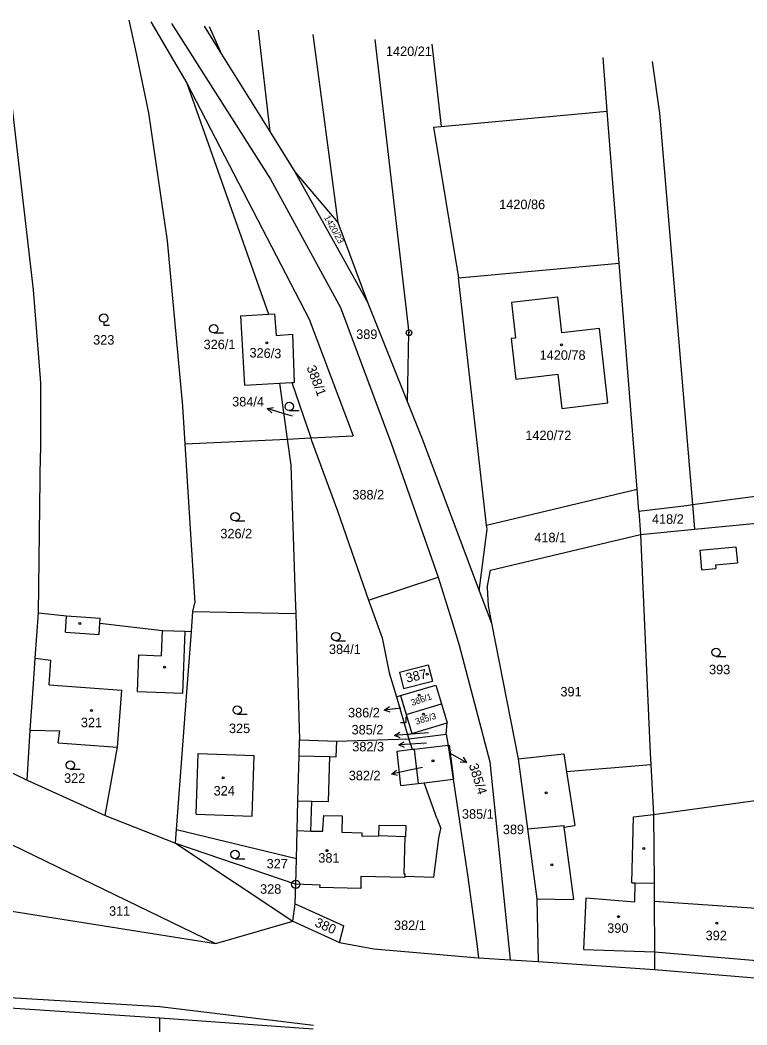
# Model space of a CAD drawing. Extents: x -779596 to -776743, y -1030330 to -1024513.
# Drawn here: x -778185.6 to -778055.6, y -1024710.7 to -1024531 of the extents above; entities that cross this region are included whole.
import ezdxf

# ---------------------------------------------------------------- set-up
doc = ezdxf.new("R2010")
doc.units = 0
for name, color, linetype in [('hranice parcel', 7, 'Continuous'), ('hranice vnitřní', 7, 'Continuous'), ('kultura', 7, 'Continuous'), ('Kód', 7, 'Continuous'), ('č_ parcel šipka', 7, 'Continuous'), ('č_pacel stav_', 7, 'Continuous'), ('č_parcel poz_', 7, 'Continuous')]:
    doc.layers.add(name, color=color, linetype=linetype)

msp = doc.modelspace()

# ---------------------------------------------------------------- linework, layer by layer
at = {"layer": 'hranice parcel'}
for points in [[(-778166.101, -1024530.961), (-778165.01, -1024536.11)], [(-778162.172, -1024531.271), (-778159.31, -1024536.15)], [(-778158.503, -1024531.561), (-778140.78, -1024559.41)], [(-778152.673, -1024532.022), (-778149.53, -1024537.06)], [(-778151.731, -1024532.097), (-778149.53, -1024537.06)], [(-778142.993, -1024532.788), (-778140.9, -1024550.9)], [(-778133.2, -1024533.562), (-778128.72, -1024567.18)], [(-778122.155, -1024534.435), (-778116.03, -1024586.88)], [(-778111.953, -1024535.242), (-778110.27, -1024549.98)], [(-778188.22, -1024535.94), (-778183.2, -1024579.2)], [(-778165.01, -1024536.11), (-778162.59, -1024547.55)], [(-778159.31, -1024536.15), (-778155.72, -1024542.27)], [(-778149.53, -1024537.06), (-778140.9, -1024550.9)], [(-778080.57, -1024547.24), (-778081.327, -1024537.663)], [(-778072.52, -1024538.359), (-778071.24, -1024547.6)], [(-778155.72, -1024542.27), (-778133.89, -1024584.45)], [(-778155.72, -1024542.27), (-778141.16, -1024583.54)], [(-778162.59, -1024547.55), (-778159.29, -1024570.46)], [(-778110.27, -1024549.98), (-778080.57, -1024547.24)], [(-778078.43, -1024574.41), (-778080.57, -1024547.24)], [(-778071.24, -1024547.6), (-778065.31, -1024617.62)], [(-778111.65, -1024550.11), (-778110.27, -1024549.98)], [(-778111.65, -1024550.11), (-778107.19, -1024577.03)], [(-778140.9, -1024550.9), (-778136.42, -1024558.08)], [(-778136.42, -1024558.08), (-778123.43, -1024581.39)], [(-778136.42, -1024558.08), (-778128.72, -1024567.18)], [(-778140.78, -1024559.41), (-778128.27, -1024582.35)], [(-778128.72, -1024567.18), (-778123.43, -1024581.39)], [(-778159.29, -1024570.46), (-778156.54, -1024599.98)], [(-778107.19, -1024577.03), (-778078.43, -1024574.41)], [(-778075.24, -1024614.87), (-778078.43, -1024574.41)], [(-778102.14, -1024621.29), (-778107.19, -1024577.03)], [(-778183.2, -1024579.2), (-778181.9, -1024595.82)], [(-778089.42, -1024580.5), (-778097.68, -1024581.48)], [(-778088.69, -1024586.87), (-778089.42, -1024580.5)], [(-778128.27, -1024582.35), (-778119.12, -1024606.78)], [(-778123.43, -1024581.39), (-778116.3, -1024599.27)], [(-778097.68, -1024581.48), (-778096.95, -1024587.84)], [(-778146.13, -1024583.85), (-778141.16, -1024583.54)], [(-778146.13, -1024583.85), (-778145.46, -1024596.25)], [(-778141.16, -1024583.54), (-778140.06, -1024583.47)], [(-778140.06, -1024583.47), (-778139.76, -1024587.37)], [(-778133.89, -1024584.45), (-778125.99, -1024605.33)], [(-778081.93, -1024586.11), (-778088.69, -1024586.87)], [(-778080.44, -1024599.44), (-778081.93, -1024586.11)], [(-778139.76, -1024587.37), (-778136.84, -1024587.15)], [(-778136.84, -1024587.15), (-778136.54, -1024595.76)], [(-778116.3, -1024599.27), (-778116.03, -1024586.88)], [(-778096.95, -1024587.84), (-778097.75, -1024587.91)], [(-778097.75, -1024587.91), (-778096.94, -1024595.18)], [(-778096.94, -1024595.18), (-778089.39, -1024594.31)], [(-778089.39, -1024594.31), (-778088.7, -1024600.4)], [(-778181.9, -1024595.82), (-778181.89, -1024608.42)], [(-778145.46, -1024596.25), (-778139.2, -1024595.91)], [(-778139.2, -1024595.91), (-778136.97, -1024595.79)], [(-778139.2, -1024595.91), (-778137.82, -1024605.88)], [(-778136.97, -1024595.79), (-778136.54, -1024595.76)], [(-778136.97, -1024595.79), (-778133.6, -1024605.68)], [(-778156.54, -1024599.98), (-778156.12, -1024606.73)], [(-778116.3, -1024599.27), (-778113.56, -1024606.14)], [(-778088.7, -1024600.4), (-778080.44, -1024599.44)], [(-778156.12, -1024606.73), (-778137.82, -1024605.88)], [(-778137.82, -1024605.88), (-778133.6, -1024605.68)], [(-778137.82, -1024605.88), (-778137.16, -1024610.58)], [(-778133.6, -1024605.68), (-778125.99, -1024605.33)], [(-778133.6, -1024605.68), (-778133.45, -1024606.15)], [(-778156.12, -1024606.73), (-778154.34, -1024635.17)], [(-778133.45, -1024606.15), (-778128.79, -1024618.71)], [(-778119.12, -1024606.78), (-778110.78, -1024630.57)], [(-778113.56, -1024606.14), (-778103.45, -1024633.03)], [(-778182.26, -1024636.99), (-778181.89, -1024608.42)], [(-778137.16, -1024610.58), (-778136.35, -1024634.3)], [(-778102.14, -1024621.29), (-778075.24, -1024614.87)], [(-778074.93, -1024618.78), (-778075.24, -1024614.87)], [(-778065.31, -1024617.62), (-778042.46, -1024614.57)], [(-778074.93, -1024618.78), (-778066.42, -1024617.77)], [(-778066.42, -1024617.77), (-778065.31, -1024617.62)], [(-778065.31, -1024617.62), (-778064.94, -1024622)], [(-778128.79, -1024618.71), (-778123.25, -1024634.7)], [(-778074.93, -1024618.78), (-778074.6, -1024622.94)], [(-778103.45, -1024633.03), (-778102.06, -1024622)], [(-778102.06, -1024622), (-778102.14, -1024621.29)], [(-778074.6, -1024622.94), (-778064.94, -1024622)], [(-778064.94, -1024622), (-778048.89, -1024620.45)], [(-778101.43, -1024629.35), (-778074.6, -1024622.94)], [(-778074.6, -1024622.94), (-778072.88, -1024662.1)], [(-778102.05, -1024632.52), (-778101.43, -1024629.35)], [(-778123.25, -1024634.7), (-778110.78, -1024630.57)], [(-778110.78, -1024630.57), (-778108.44, -1024638.2)], [(-778102.05, -1024632.52), (-778101.89, -1024635.72)], [(-778136.35, -1024634.3), (-778136.25, -1024637.07)], [(-778123.25, -1024634.7), (-778120.79, -1024641.44)], [(-778103.45, -1024633.03), (-778101.27, -1024638.84)], [(-778154.66, -1024636.73), (-778154.34, -1024635.17)], [(-778101.89, -1024635.72), (-778101.27, -1024638.84)], [(-778182.84, -1024645.1), (-778182.26, -1024636.99)], [(-778182.26, -1024636.99), (-778177.25, -1024637.52)], [(-778177.25, -1024637.52), (-778171.26, -1024637.91)], [(-778171.32, -1024638.81), (-778171.26, -1024637.91)], [(-778154.93, -1024640.32), (-778154.66, -1024636.73)], [(-778154.66, -1024636.73), (-778136.25, -1024637.07)], [(-778136.25, -1024637.07), (-778135.58, -1024659.69)], [(-778108.44, -1024638.2), (-778107.04, -1024642.76)], [(-778171.32, -1024638.81), (-778160.08, -1024640.12)], [(-778160.08, -1024640.12), (-778156.04, -1024640.27)], [(-778101.27, -1024638.84), (-778096.49, -1024663.08)], [(-778156.04, -1024640.27), (-778154.93, -1024640.32)], [(-778155.8, -1024651.95), (-778154.93, -1024640.32)], [(-778120.79, -1024641.44), (-778119.56, -1024647.69)], [(-778107.04, -1024642.76), (-778101.56, -1024663.63)], [(-778183.16, -1024649.64), (-778182.84, -1024645.1)], [(-778117.72, -1024647.59), (-778112.59, -1024646.28)], [(-778112.59, -1024646.28), (-778111.84, -1024649.19)], [(-778119.56, -1024647.69), (-778118.28, -1024651.99)], [(-778117.72, -1024647.59), (-778116.98, -1024650.51)], [(-778183.79, -1024657.94), (-778183.16, -1024649.64)], [(-778117.52, -1024651.76), (-778111.21, -1024649.88)], [(-778116.98, -1024650.51), (-778111.84, -1024649.19)], [(-778111.21, -1024649.88), (-778110.2, -1024653.27)], [(-778157.58, -1024675.7), (-778155.8, -1024651.95)], [(-778118.28, -1024651.99), (-778117.52, -1024651.76)], [(-778118.28, -1024651.99), (-778116.26, -1024658.77)], [(-778117.52, -1024651.76), (-778116.5, -1024655.15)], [(-778116.5, -1024655.15), (-778110.2, -1024653.27)], [(-778110.2, -1024653.27), (-778109.19, -1024656.66)], [(-778116.5, -1024655.15), (-778115.49, -1024658.54)], [(-778184.31, -1024666.91), (-778183.79, -1024657.94)], [(-778183.79, -1024657.94), (-778178.45, -1024658.1)], [(-778178.77, -1024660.2), (-778178.45, -1024658.1)], [(-778115.49, -1024658.54), (-778109.19, -1024656.66)], [(-778109.35, -1024658.65), (-778109.19, -1024656.66)], [(-778201.09, -1024658.8), (-778184.31, -1024666.91)], [(-778135.65, -1024662.56), (-778135.58, -1024659.69)], [(-778135.58, -1024659.69), (-778128.92, -1024659.91)], [(-778128.92, -1024659.91), (-778116.03, -1024659.53)], [(-778116.26, -1024658.77), (-778115.49, -1024658.54)], [(-778116.26, -1024658.77), (-778116.03, -1024659.53)], [(-778116.03, -1024659.53), (-778109.35, -1024658.65)], [(-778115.37, -1024661.42), (-778116.03, -1024659.53)], [(-778109.35, -1024658.65), (-778109.04, -1024660.69)], [(-778178.77, -1024660.2), (-778168.17, -1024660.97)], [(-778170.34, -1024673.22), (-778168.17, -1024660.97)], [(-778115.37, -1024661.42), (-778118.19, -1024661.76)], [(-778115.08, -1024661.39), (-778115.37, -1024661.42)], [(-778109.04, -1024660.69), (-778115.08, -1024661.39)], [(-778109.04, -1024660.69), (-778108.81, -1024660.66)], [(-778109.04, -1024660.69), (-778108.13, -1024666.73)], [(-778108.81, -1024660.66), (-778108.07, -1024666.73)], [(-778154.07, -1024672.99), (-778153.71, -1024662.15)], [(-778153.71, -1024662.15), (-778143.72, -1024662.48)], [(-778144.08, -1024673.32), (-778143.72, -1024662.48)], [(-778135.88, -1024670.57), (-778135.65, -1024662.56)], [(-778118.19, -1024661.76), (-778117.53, -1024667.82)], [(-778096.49, -1024663.08), (-778088.36, -1024662.21)], [(-778096.49, -1024663.08), (-778094.83, -1024675.59)], [(-778088.36, -1024662.21), (-778087.88, -1024665.34)], [(-778072.88, -1024662.1), (-778072.77, -1024664.1)], [(-778101.56, -1024663.63), (-778097.93, -1024699.01)], [(-778087.88, -1024665.34), (-778072.77, -1024664.1)], [(-778072.77, -1024664.1), (-778072.27, -1024673.03)], [(-778184.31, -1024666.91), (-778170.34, -1024673.22)], [(-778113.29, -1024667.35), (-778108.13, -1024666.73)], [(-778108.13, -1024666.73), (-778105.48, -1024684.24)], [(-778108.07, -1024666.73), (-778108.13, -1024666.73)], [(-778117.53, -1024667.82), (-778114.37, -1024667.47)], [(-778114.37, -1024667.47), (-778113.29, -1024667.35)], [(-778111.05, -1024673.72), (-778113.29, -1024667.35)], [(-778136.03, -1024675.91), (-778135.88, -1024670.57)], [(-778072.27, -1024673.03), (-778047.16, -1024669.58)], [(-778170.34, -1024673.22), (-778157.77, -1024678.19)], [(-778154.07, -1024672.99), (-778144.08, -1024673.32)], [(-778111.05, -1024673.72), (-778110.33, -1024675.52)], [(-778072.27, -1024673.03), (-778072.19, -1024685.34)], [(-778193.66, -1024675.24), (-778174.57, -1024684.5)], [(-778157.77, -1024678.19), (-778157.58, -1024675.7)], [(-778157.58, -1024675.7), (-778136.16, -1024680.88)], [(-778136.16, -1024680.88), (-778136.03, -1024675.91)], [(-778110.69, -1024677.28), (-778110.33, -1024675.52)], [(-778094.83, -1024675.59), (-778093.18, -1024688.11)], [(-778111.6, -1024684.24), (-778110.69, -1024677.28)], [(-778157.77, -1024678.19), (-778136.79, -1024692.14)], [(-778157.77, -1024678.19), (-778136.27, -1024685.52)], [(-778136.27, -1024685.52), (-778136.16, -1024680.88)], [(-778174.57, -1024684.5), (-778150.63, -1024696.12)], [(-778124.61, -1024684.13), (-778124.66, -1024686.25)], [(-778116.78, -1024684.3), (-778124.61, -1024684.13)], [(-778116.78, -1024684.07), (-778111.6, -1024684.24)], [(-778116.78, -1024684.07), (-778116.78, -1024684.3)], [(-778105.48, -1024684.24), (-778103.97, -1024695.71)], [(-778136.4, -1024689.02), (-778136.27, -1024685.52)], [(-778131.92, -1024685.69), (-778136.27, -1024685.52)], [(-778131.94, -1024686.11), (-778131.92, -1024685.69)], [(-778124.66, -1024686.25), (-778131.94, -1024686.11)], [(-778072.19, -1024685.34), (-778072.17, -1024688.53)], [(-778093.18, -1024688.11), (-778092.94, -1024699.3)], [(-778072.17, -1024688.53), (-778072.11, -1024697.57)], [(-778195.72, -1024688.95), (-778150.63, -1024696.12)], [(-778136.79, -1024692.14), (-778136.4, -1024689.02)], [(-778136.4, -1024689.02), (-778127.67, -1024692.93)], [(-778148.71, -1024695.55), (-778136.79, -1024692.14)], [(-778136.79, -1024692.14), (-778128.43, -1024695.93)], [(-778128.43, -1024695.93), (-778127.67, -1024692.93)], [(-778150.63, -1024696.12), (-778148.71, -1024695.55)], [(-778103.97, -1024695.71), (-778103.58, -1024698.68)], [(-778128.43, -1024695.93), (-778122.31, -1024697.09)], [(-778122.31, -1024697.09), (-778103.58, -1024698.68)], [(-778072.11, -1024697.57), (-778072.09, -1024700.76)], [(-778103.58, -1024698.68), (-778097.93, -1024699.01)], [(-778097.93, -1024699.01), (-778092.94, -1024699.3)], [(-778092.94, -1024699.3), (-778072.09, -1024700.76)], [(-778072.09, -1024700.76), (-778049.13, -1024702.66)], [(-778198.44, -1024705.1), (-778160.55, -1024707.39)], [(-778188.31, -1024707.53), (-778160.55, -1024709.39)], [(-778160.55, -1024707.39), (-778133.07, -1024710.69)], [(-778160.63, -1024741.23), (-778160.55, -1024709.39)], [(-778160.55, -1024709.39), (-778133.13, -1024711.38)]]:
    msp.add_lwpolyline(points, dxfattribs=at)
at = {"layer": 'hranice vnitřní'}
for points in [[(-778064.02, -1024625.76), (-778057.56, -1024625.18)], [(-778057.56, -1024625.18), (-778057.3, -1024628.03)], [(-778064.02, -1024625.76), (-778063.7, -1024629.28)], [(-778063.7, -1024629.28), (-778061.13, -1024629.05)], [(-778061.19, -1024628.38), (-778057.3, -1024628.03)], [(-778061.19, -1024628.38), (-778061.13, -1024629.05)], [(-778177.44, -1024640.43), (-778177.25, -1024637.52)], [(-778171.45, -1024640.82), (-778171.32, -1024638.81)], [(-778160.25, -1024644.64), (-778160.08, -1024640.12)], [(-778177.44, -1024640.43), (-778171.45, -1024640.82)], [(-778156.47, -1024651.35), (-778156.04, -1024640.27)], [(-778182.84, -1024645.1), (-778180.07, -1024645.46)], [(-778180.39, -1024649.84), (-778180.07, -1024645.46)], [(-778164.59, -1024651.04), (-778164.34, -1024644.49)], [(-778164.34, -1024644.49), (-778160.25, -1024644.64)], [(-778180.39, -1024649.84), (-778167.34, -1024650.8)], [(-778168.17, -1024660.97), (-778167.34, -1024650.8)], [(-778164.59, -1024651.04), (-778156.47, -1024651.35)], [(-778129.06, -1024662.75), (-778128.92, -1024659.91)], [(-778115.08, -1024661.39), (-778114.37, -1024667.47)], [(-778135.65, -1024662.56), (-778130.18, -1024662.67)], [(-778130.4, -1024670.72), (-778130.18, -1024662.67)], [(-778130.18, -1024662.67), (-778129.06, -1024662.75)], [(-778087.88, -1024665.34), (-778086.39, -1024675)], [(-778135.88, -1024670.57), (-778133.4, -1024670.64)], [(-778133.55, -1024676.01), (-778133.4, -1024670.64)], [(-778133.4, -1024670.64), (-778130.4, -1024670.72)], [(-778131.4, -1024675.58), (-778131.22, -1024673.24)], [(-778131.22, -1024673.24), (-778127.99, -1024673.28)], [(-778127.99, -1024673.28), (-778128.03, -1024676.18)], [(-778076.15, -1024685.25), (-778075.9, -1024673.46)], [(-778075.9, -1024673.46), (-778072.27, -1024673.03)], [(-778136.03, -1024675.91), (-778133.55, -1024676.01)], [(-778133.55, -1024676.01), (-778131.43, -1024676.04)], [(-778131.43, -1024676.04), (-778131.4, -1024675.58)], [(-778121.39, -1024676.85), (-778121.37, -1024674.96)], [(-778121.37, -1024674.96), (-778116.59, -1024675.03)], [(-778116.59, -1024675.03), (-778116.64, -1024677.05)], [(-778094.83, -1024675.59), (-778088.34, -1024674.99)], [(-778088.34, -1024674.99), (-778088.31, -1024675.28)], [(-778088.31, -1024675.28), (-778086.39, -1024675)], [(-778088.31, -1024675.28), (-778086.59, -1024688.24)], [(-778128.03, -1024676.18), (-778124.45, -1024676.33)], [(-778124.45, -1024676.33), (-778124.46, -1024676.91)], [(-778124.46, -1024676.91), (-778121.39, -1024676.85)], [(-778116.78, -1024677.05), (-778121.39, -1024676.85)], [(-778116.78, -1024677.05), (-778116.94, -1024683.65)], [(-778116.64, -1024677.05), (-778116.78, -1024677.05)], [(-778116.94, -1024683.65), (-778116.77, -1024683.65)], [(-778116.77, -1024683.65), (-778116.78, -1024684.07)], [(-778076.15, -1024685.25), (-778075.55, -1024685.27)], [(-778075.62, -1024688.65), (-778075.55, -1024685.27)], [(-778075.55, -1024685.27), (-778072.19, -1024685.34)], [(-778093.18, -1024688.11), (-778086.59, -1024688.24)], [(-778084.76, -1024697.18), (-778084.33, -1024687.93)], [(-778084.33, -1024687.93), (-778075.62, -1024688.65)], [(-778072.17, -1024688.53), (-778053.89, -1024689.78)], [(-778084.76, -1024697.18), (-778072.11, -1024697.57)], [(-778072.11, -1024697.57), (-778048.92, -1024699.55)]]:
    msp.add_lwpolyline(points, dxfattribs=at)
at = {"layer": 'kultura'}
for points in [[(-778170.6, -1024585.01), (-778170.6, -1024585.51), (-778169.577, -1024585.51)], [(-778150.94, -1024586.91), (-778149.19, -1024586.91)], [(-778137.43, -1024600.8), (-778135.68, -1024600.8)], [(-778147.1, -1024620.54), (-778145.35, -1024620.54)], [(-778129.1, -1024641.96), (-778127.35, -1024641.96)], [(-778061.1, -1024644.78), (-778059.35, -1024644.78)], [(-778146.73, -1024655.1), (-778144.98, -1024655.1)], [(-778117.53, -1024656.58), (-778116.53, -1024656.58), (-778116.53, -1024655.58)], [(-778176.58, -1024664.94), (-778174.83, -1024664.94)], [(-778147.13, -1024680.94), (-778145.38, -1024680.94)]]:
    msp.add_lwpolyline(points, dxfattribs=at)
for centre, radius in [((-778170.6, -1024584.26), 0.75), ((-778150.94, -1024586.16), 0.75), ((-778141.43, -1024588.68), 0.175), ((-778088.73, -1024589.02), 0.175), ((-778137.43, -1024600.05), 0.75), ((-778147.1, -1024619.79), 0.75), ((-778174.89, -1024638.87), 0.175), ((-778129.1, -1024641.21), 0.75), ((-778061.1, -1024644.03), 0.75), ((-778159.72, -1024646.67), 0.175), ((-778112.76, -1024647.92), 0.175), ((-778114.19, -1024651.69), 0.175), ((-778172.78, -1024654.46), 0.175), ((-778146.73, -1024654.35), 0.75), ((-778113.43, -1024655.1), 0.175), ((-778108.89, -1024660.84), 0.118), ((-778176.58, -1024664.19), 0.75), ((-778111.73, -1024663.43), 0.175), ((-778149.26, -1024666.47), 0.175), ((-778091.49, -1024669.14), 0.175), ((-778147.13, -1024680.19), 0.75), ((-778130.68, -1024679.5), 0.175), ((-778074.02, -1024679.12), 0.175), ((-778090.47, -1024682.06), 0.175), ((-778078.57, -1024691.31), 0.175), ((-778060.97, -1024692.48), 0.175)]:
    msp.add_circle(centre, radius, dxfattribs=at)
at = {"layer": 'Kód'}
for centre, radius in [((-778116.03, -1024586.88), 0.5), ((-778116.03, -1024586.88), 0.032), ((-778136.27, -1024685.52), 0.75), ((-778136.27, -1024685.52), 0.032)]:
    msp.add_circle(centre, radius, dxfattribs=at)
at = {"layer": 'č_ parcel šipka'}
for points in [[(-778140.559, -1024601.215), (-778141.377, -1024600.453), (-778140.277, -1024600.256)], [(-778138.5, -1024601.3), (-778141.377, -1024600.453)], [(-778136.87, -1024601.78), (-778138.5, -1024601.3)], [(-778119.413, -1024654.736), (-778120.461, -1024654.349), (-778119.522, -1024653.743)], [(-778117.48, -1024654.02), (-778120.461, -1024654.349)], [(-778117.584, -1024659.335), (-778118.62, -1024658.915), (-778117.663, -1024658.339)], [(-778115.63, -1024658.68), (-778118.62, -1024658.915)], [(-778112.56, -1024658.44), (-778115.63, -1024658.68)], [(-778116.826, -1024661.037), (-778117.854, -1024660.597), (-778116.886, -1024660.04)], [(-778114.86, -1024660.42), (-778117.854, -1024660.597)], [(-778112.91, -1024660.3), (-778114.86, -1024660.42)], [(-778108.75, -1024661.99), (-778108.34, -1024662.23)], [(-778108.34, -1024662.23), (-778105.748, -1024663.739)], [(-778106.36, -1024662.803), (-778105.748, -1024663.739), (-778106.863, -1024663.668)], [(-778118.06, -1024666.078), (-778119.143, -1024665.798), (-778118.27, -1024665.101)], [(-778116.21, -1024665.17), (-778119.143, -1024665.798)], [(-778113.63, -1024664.61), (-778116.21, -1024665.17)]]:
    msp.add_lwpolyline(points, dxfattribs=at)

# ---------------------------------------------------------------- texts
for s, p in [('389', (-778125.46, -1024587.99)), ('384/4', (-778147.643, -1024600.05)), ('386/2', (-778126.92, -1024655.67)), ('385/2', (-778126.29, -1024658.72)), ('382/3', (-778126.16, -1024661.75)), ('382/2', (-778126.79, -1024666.91)), ('389', (-778099.23, -1024676.55))]:
    msp.add_text(s, height=1.7, dxfattribs=at).set_placement(p)
msp.add_text('385/4', height=1.7, rotation=287.70229, dxfattribs=at).set_placement((-778105.349, -1024664.199))
at = {"layer": 'č_pacel stav_'}
for s, height, rotation, p in [('326/3', 1.7, 358.20285, (-778144.564, -1024591.277)), ('387', 1.7, 12.5001, (-778116.389, -1024649.472)), ('386/1', 1.14, 18.70015, (-778115.445, -1024653.617)), ('385/3', 1.14, 16.80013, (-778114.707, -1024656.991))]:
    msp.add_text(s, height=height, rotation=rotation, dxfattribs=at).set_placement(p)
for s, height, p in [('1420/78', 1.7, (-778092.66, -1024591.72)), ('386/2', 0.1, (-778117.28, -1024653.82)), ('321', 1.7, (-778174.69, -1024657.42)), ('385/4', 0.1, (-778108.59, -1024661.58)), ('382/2', 0.1, (-778113.28, -1024664.25)), ('324', 1.7, (-778150.95, -1024669.64)), ('381', 1.7, (-778132.23, -1024681.65)), ('390', 1.7, (-778080.57, -1024694.2)), ('392', 1.7, (-778062.97, -1024695.52))]:
    msp.add_text(s, height=height, dxfattribs=at).set_placement(p)
at = {"layer": 'č_parcel poz_'}
for s, height, rotation, p in [('1420/21', 1.7, 359.90286, (-778120.14, -1024537.381)), ('1420/23', 1.14, 299.20238, (-778131.258, -1024566.257)), ('388/1', 1.7, 290.90231, (-778134.362, -1024593.085)), ('380', 1.7, 336.10267, (-778133.007, -1024692.959))]:
    msp.add_text(s, height=height, rotation=rotation, dxfattribs=at).set_placement(p)
for s, height, p in [('1420/86', 1.7, (-778099.89, -1024564.77)), ('323', 1.7, (-778172.5, -1024589)), ('326/1', 1.7, (-778152.75, -1024589.81)), ('384/4', 0.1, (-778136.836, -1024601.58)), ('1420/72', 1.7, (-778095.216, -1024606.08)), ('388/2', 1.7, (-778126.15, -1024616.69)), ('418/2', 1.7, (-778072.57, -1024621.05)), ('326/2', 1.7, (-778149.75, -1024623.65)), ('418/1', 1.7, (-778093.61, -1024624.36)), ('384/1', 1.7, (-778130.33, -1024644.33)), ('393', 1.7, (-778062.36, -1024647.96)), ('391', 1.7, (-778088.94, -1024651.92)), ('325', 1.7, (-778148.21, -1024658.48)), ('385/2', 0.1, (-778111.43, -1024658.1)), ('382/3', 0.1, (-778113.47, -1024660.63)), ('322', 1.7, (-778177.7, -1024667.38)), ('385/1', 1.7, (-778106.55, -1024673.79)), ('327', 1.7, (-778141.48, -1024682.68)), ('328', 1.7, (-778142.65, -1024687.21)), ('311', 1.7, (-778169.66, -1024691.15)), ('382/1', 1.7, (-778118.7, -1024693.7))]:
    msp.add_text(s, height=height, dxfattribs=at).set_placement(p)

doc.saveas('drawing.dxf')
